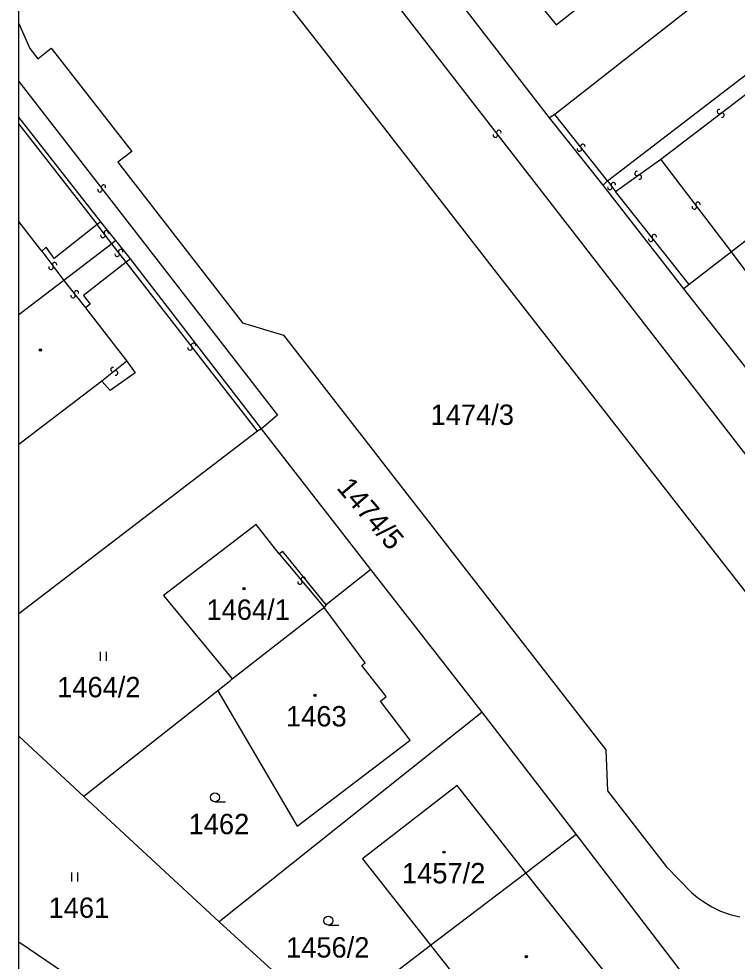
# Model space of a CAD drawing. Extents: x -600391 to -599491, y -1160176 to -1159402.
# Drawn here: x -600391 to -600331.1, y -1159991 to -1159912.4 of the extents above; entities that cross this region are included whole.
import ezdxf

# ---------------------------------------------------------------- set-up
doc = ezdxf.new("R2010")
doc.units = 0
for name, color, linetype in [('Level 1', 7, 'Continuous'), ('Level 13', 7, 'Continuous'), ('Level 3', 7, 'Continuous'), ('Level 4', 7, 'Continuous'), ('Level 5', 7, 'Continuous'), ('Vrstva 63', 7, 'Continuous')]:
    doc.layers.add(name, color=color, linetype=linetype)

msp = doc.modelspace()

# ---------------------------------------------------------------- linework, layer by layer
at = {"layer": 'Level 1'}
for p, q in [((-600384.17, -1159929.3), (-600391.008, -1159920.581)), ((-600389.09, -1159931.75), (-600391.008, -1159929.264)), ((-600387.26, -1159934.2), (-600391.008, -1159937.064)), ((-600384.09, -1159942.6), (-600391.008, -1159947.869)), ((-600371.11, -1159946.75), (-600391.008, -1159962.008)), ((-600385.58, -1159977.24), (-600391.008, -1159972.206))]:
    msp.add_line(p, q, dxfattribs=at)
for points in [[(-600352.73, -1159904.77), (-600346.2, -1159912.88), (-600337.36, -1159905.88), (-600343.74, -1159898.17)], [(-600376.7, -1159900.77), (-600365.93, -1159914.53), (-600350.97, -1159933.8), (-600318.93, -1159974.9), (-600315.13, -1159979.92)], [(-600321.66, -1159901), (-600346.31, -1159920.36)], [(-600346.75, -1159920.64), (-600356.54, -1159907.96)], [(-600391.008, -1159912.765), (-600390.09, -1159914.85), (-600389.43, -1159915.71), (-600388.3, -1159914.82), (-600381.6, -1159923.44), (-600382.75, -1159924.32), (-600372.35, -1159937.72), (-600368.95, -1159938.76), (-600342.07, -1159973.35), (-600341.91, -1159976.76), (-600337, -1159983.1), (-600334.91, -1159985.23), (-600334.41, -1159985.67), (-600333.9, -1159986.03), (-600333.21, -1159986.45), (-600332.49, -1159986.79), (-600331.69, -1159987.07), (-600330.88, -1159987.27)], [(-600341.92, -1159925.88), (-600328.23, -1159915.36)], [(-600346.31, -1159920.36), (-600346.75, -1159920.64)], [(-600342.29, -1159926.24), (-600346.75, -1159920.64)], [(-600321.47, -1159923.97), (-600331.59, -1159931.8)], [(-600321.47, -1159923.97), (-600315.76, -1159931.77), (-600325.9, -1159939.4), (-600331.59, -1159931.8)], [(-600342.29, -1159926.24), (-600341.92, -1159925.88)], [(-600335.56, -1159934.9), (-600342.29, -1159926.24)], [(-600384.48, -1159929.52), (-600388.05, -1159932.35), (-600388.72, -1159931.42), (-600389.09, -1159931.75)], [(-600384.17, -1159929.3), (-600384.48, -1159929.52)], [(-600382.92, -1159930.87), (-600384.17, -1159929.3)], [(-600383.25, -1159931.13), (-600387.26, -1159934.2)], [(-600382.92, -1159930.87), (-600383.25, -1159931.13)], [(-600381.71, -1159932.38), (-600382.92, -1159930.87)], [(-600331.59, -1159931.8), (-600335.1, -1159934.54)], [(-600382.07, -1159932.67), (-600385.62, -1159935.45), (-600385.07, -1159936.17), (-600385.44, -1159936.48)], [(-600381.71, -1159932.38), (-600382.07, -1159932.67)], [(-600370.76, -1159946.56), (-600381.71, -1159932.38)], [(-600335.1, -1159934.54), (-600335.56, -1159934.9)], [(-600325.43, -1159947.74), (-600335.56, -1159934.9)], [(-600385.44, -1159936.48), (-600382.01, -1159940.93)], [(-600382.01, -1159940.93), (-600381.31, -1159941.89), (-600383.4, -1159943.38), (-600384.09, -1159942.6)], [(-600370.76, -1159946.56), (-600371.11, -1159946.75)], [(-600361.66, -1159958.31), (-600370.76, -1159946.56)], [(-600369.31, -1159957), (-600371.22, -1159954.56), (-600378.95, -1159960.48), (-600373.22, -1159967.43)], [(-600365.38, -1159961.25), (-600368.99, -1159956.81), (-600369.31, -1159957)], [(-600361.66, -1159958.31), (-600365.38, -1159961.25)], [(-600352.36, -1159970.2), (-600361.66, -1159958.31)], [(-600374.42, -1159968.43), (-600367.8, -1159979.72), (-600358.38, -1159972.53), (-600360.85, -1159969.29), (-600360.38, -1159968.9), (-600362.41, -1159966.32), (-600362.14, -1159966.08), (-600365.55, -1159961.46)], [(-600373.22, -1159967.43), (-600365.94, -1159961.74), (-600365.55, -1159961.46)], [(-600365.38, -1159961.25), (-600365.55, -1159961.46)], [(-600373.22, -1159967.43), (-600373.47, -1159967.68), (-600374.42, -1159968.43)], [(-600374.42, -1159968.43), (-600385.58, -1159977.24)], [(-600352.36, -1159970.2), (-600374.29, -1159987.69)], [(-600344.54, -1159980.38), (-600352.36, -1159970.2)], [(-600348.73, -1159983.59), (-600354.45, -1159976.31), (-600362.34, -1159982.44), (-600356.68, -1159989.64)], [(-600374.29, -1159987.69), (-600385.58, -1159977.24)], [(-600348.73, -1159983.59), (-600344.54, -1159980.38)], [(-600332.77, -1159995.76), (-600344.54, -1159980.38)], [(-600356.68, -1159989.64), (-600348.71, -1159999.77), (-600340.84, -1159993.54), (-600348.73, -1159983.59)], [(-600356.68, -1159989.64), (-600348.73, -1159983.59)], [(-600374.29, -1159987.69), (-600369.9, -1159991.69)], [(-600391.008, -1160003.79), (-600388.51, -1160005.48), (-600381.83, -1159995.61), (-600391.008, -1159989.394)], [(-600365.16, -1159996.14), (-600356.68, -1159989.64)]]:
    msp.add_lwpolyline(points, dxfattribs=at)
at = {"layer": 'Level 13'}
for centre, start, end in [((-600332.591, -1159920.102), 74.76109, 306.85909), ((-600332.369, -1159920.397), 254.54663, 127.13663), ((-600350.983, -1159921.848), 345.15104, 217.24904), ((-600351.276, -1159922.072), 164.93659, 37.52659), ((-600344.265, -1159923.233), 165.86761, 37.96561), ((-600343.975, -1159923.006), 345.65315, 218.24315), ((-600339.466, -1159925.269), 72.85271, 304.95071), ((-600339.254, -1159925.57), 252.63826, 125.22826), ((-600383.953, -1159926.408), 345.13848, 217.23648), ((-600341.726, -1159926.432), 164.85252, 37.44252), ((-600341.433, -1159926.209), 345.06698, 217.16497), ((-600384.246, -1159926.632), 164.92402, 37.51402), ((-600334.678, -1159928.051), 164.71467, 36.81267), ((-600334.383, -1159927.829), 344.50022, 217.09022), ((-600384.008, -1159930.441), 164.75166, 36.84966), ((-600383.713, -1159930.219), 344.53721, 217.12721), ((-600338.025, -1159930.537), 345.43889, 218.02889), ((-600338.316, -1159930.763), 165.65334, 37.75134), ((-600382.807, -1159932.011), 164.83329, 36.93129), ((-600382.513, -1159931.789), 344.61883, 217.20883), ((-600388.031, -1159932.871), 344.13021, 216.22821), ((-600388.328, -1159933.089), 163.91576, 36.50576), ((-600386.205, -1159935.226), 345.9712, 218.06919), ((-600386.494, -1159935.454), 165.75674, 38.34674), ((-600376.737, -1159939.822), 165.27025, 37.36824), ((-600376.444, -1159939.598), 345.05579, 217.64579), ((-600383.165, -1159941.626), 75.91872, 308.50872), ((-600382.936, -1159941.915), 256.13318, 128.23118), ((-600367.571, -1159959.348), 167.29082, 39.88082), ((-600367.288, -1159959.112), 347.50528, 219.60327)]:
    msp.add_arc(centre, 0.184, start, end, dxfattribs=at)
at = {"layer": 'Level 3'}
msp.add_line((-600391.008, -1159921.161), (-600384.48, -1159929.52), dxfattribs=at)
for points in [[(-600373.58, -1159893), (-600328.68, -1159950.93)], [(-600337.48, -1159924.08), (-600327.47, -1159916.43)], [(-600391.008, -1159917.603), (-600369.45, -1159945.43), (-600370.76, -1159946.56)], [(-600341.92, -1159925.88), (-600346.31, -1159920.36)], [(-600341.24, -1159926.76), (-600337.48, -1159924.08)], [(-600331.59, -1159931.8), (-600337.48, -1159924.08)], [(-600341.92, -1159925.88), (-600341.24, -1159926.76)], [(-600335.1, -1159934.54), (-600341.24, -1159926.76)], [(-600383.25, -1159931.13), (-600384.48, -1159929.52)], [(-600382.07, -1159932.67), (-600383.25, -1159931.13)], [(-600389.09, -1159931.75), (-600387.26, -1159934.2)], [(-600371.11, -1159946.75), (-600382.07, -1159932.67)], [(-600387.26, -1159934.2), (-600385.44, -1159936.48)], [(-600382.01, -1159940.93), (-600384.09, -1159942.6)], [(-600369.31, -1159957), (-600365.55, -1159961.46)]]:
    msp.add_lwpolyline(points, dxfattribs=at)
at = {"layer": 'Level 5'}
for p, q in [((-600384.21, -1159965.915), (-600384.21, -1159965.164)), ((-600383.71, -1159965.915), (-600383.71, -1159965.164)), ((-600374.66, -1159977.68), (-600373.785, -1159977.68)), ((-600386.6, -1159984.325), (-600386.6, -1159983.574)), ((-600386.1, -1159984.325), (-600386.1, -1159983.574)), ((-600365.19, -1159987.97), (-600364.315, -1159987.97))]:
    msp.add_line(p, q, dxfattribs=at)
for centre, radius in [((-600389.21, -1159939.99), 0.09), ((-600389.21, -1159939.99), 0.0521), ((-600372.24, -1159959.9), 0.09), ((-600372.24, -1159959.9), 0.0521), ((-600366.32, -1159968.79), 0.09), ((-600366.32, -1159968.79), 0.0521), ((-600374.66, -1159977.305), 0.375), ((-600355.56, -1159981.88), 0.09), ((-600355.56, -1159981.88), 0.0521), ((-600365.19, -1159987.595), 0.375), ((-600348.69, -1159990.59), 0.09), ((-600348.69, -1159990.59), 0.0521)]:
    msp.add_circle(centre, radius, dxfattribs=at)
at = {"layer": 'Vrstva 63'}
msp.add_lwpolyline([(-600391.008, -1159401.769), (-599490.773, -1159401.769), (-599490.773, -1160176.079), (-600391.008, -1160176.079)], close=True, dxfattribs=at)

# ---------------------------------------------------------------- texts
at = {"layer": 'Level 4'}
for s, p in [('1474/3', (-600356.67, -1159946.24)), ('1464/1', (-600375.363, -1159962.5)), ('1464/2', (-600387.815, -1159968.96)), ('1463', (-600368.732, -1159971.39)), ('1462', (-600376.85, -1159980.38)), ('1457/2', (-600359.061, -1159984.48)), ('1461', (-600388.528, -1159987.36)), ('1456/2', (-600368.727, -1159990.67))]:
    msp.add_text(s, height=1.7, dxfattribs=at).set_placement(p)
msp.add_text('1474/5', height=1.7, rotation=310.56426, dxfattribs=at).set_placement((-600364.57, -1159951.53))

doc.saveas('drawing.dxf')
